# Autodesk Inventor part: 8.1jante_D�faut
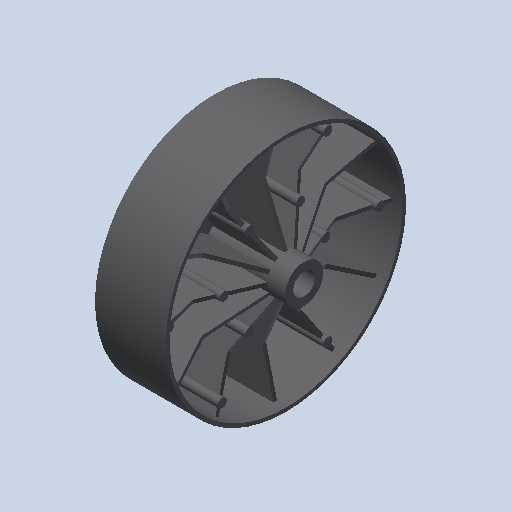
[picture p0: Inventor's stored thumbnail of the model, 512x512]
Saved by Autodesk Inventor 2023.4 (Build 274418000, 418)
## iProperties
Created: 2011-01
Part Number: 8.1jante_D�faut
Document SubType Name: Modeling
Designer: eric
Density: 1 g/cm^3
Mass: 113.684 g
Surface Area: 1044.9 cm^2
Volume: 113.684 cm^3
Material: Générique
Appearance: Yellow
Author: eric
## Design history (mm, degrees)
feature "Base1"
node "Corps solides"
node "Corps surfaciques"
node "Solide1"
